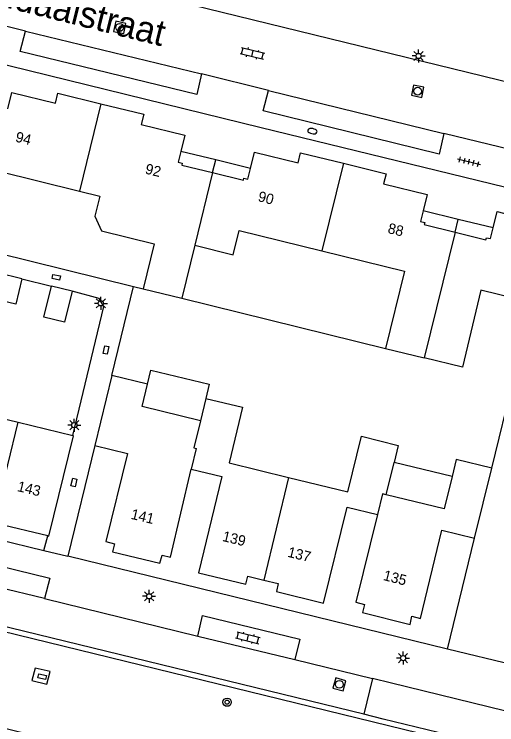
# Model space of a CAD drawing. Extents: x 125000 to 129004, y 397500 to 399008.
# Drawn here: x 126346.7 to 126393.1, y 398600 to 398668.3 of the extents above; entities that cross this region are included whole.
import ezdxf

# ---------------------------------------------------------------- set-up
doc = ezdxf.new("R2010")
doc.units = 0
for name, color, linetype in [('gg-afsc-erfafscheiding', 7, 'Continuous'), ('gg-afsc-hekwerk', 7, 'Continuous'), ('gg-afsc-muur', 7, 'Continuous'), ('gg-anno-huisnummerreeks BGT', 7, 'Continuous'), ('gg-anno-openbare ruimte label', 7, 'Continuous'), ('gg-bbg-bijgebouw', 7, 'Continuous'), ('gg-bbg-gedigitaliseerde bebouwing', 7, 'Continuous'), ('gg-bbg-hoofdgebouw', 7, 'Continuous'), ('gg-bbg-luifel en loopbrug', 7, 'Continuous'), ('gg-bbg-tussenscheiding', 7, 'Continuous'), ('gg-knt-verharding', 7, 'Continuous'), ('gg-knt-verharding nz', 7, 'Continuous'), ('gt-grn-weggrens', 7, 'Continuous'), ('gt-symb-boom', 7, 'Continuous'), ('gt-symb-brandkraan', 7, 'Continuous'), ('gt-symb-klinker verharding', 7, 'Continuous'), ('gt-symb-kolk center center', 7, 'Continuous'), ('gt-symb-lichtmast', 7, 'Continuous'), ('gt-symb-rioolschacht', 7, 'Continuous'), ('gt-symb-tegel verharding', 7, 'Continuous')]:
    doc.layers.add(name, color=color, linetype=linetype)

# ---------------------------------------------------------------- blocks, each defined once
blk = doc.blocks.new('gt0-RS')
at = {"layer": 'gt-symb-rioolschacht'}
blk.add_lwpolyline([(-0.5, -0.5), (0.5, -0.5), (0.5, 0.5), (-0.5, 0.5)], close=True, dxfattribs=at)
blk.add_circle((0, 0), 0.375, dxfattribs=at)
blk = doc.blocks.new('gt0-KL1')
at = {"layer": 'gt-symb-klinker verharding'}
for p, q in [((-1.15, 0.3), (1.15, 0.3)), ((-1, -0.3), (-1, 0.3)), ((-0.5, 0.3), (-0.5, 0.45)), ((0, -0.3), (0, 0.3)), ((0.5, 0.3), (0.5, 0.45)), ((1, -0.3), (1, 0.3)), ((-1.15, -0.3), (1.15, -0.3)), ((-0.5, -0.45), (-0.5, -0.3)), ((0.5, -0.45), (0.5, -0.3))]:
    blk.add_line(p, q, dxfattribs=at)
blk = doc.blocks.new('gt0-LMAST')
at = {"layer": 'gt-symb-lichtmast'}
for p, q in [((-0.182, 0.173), (-0.447, 0.438)), ((-0.005, 0.246), (-0.005, 0.621)), ((0.172, 0.173), (0.437, 0.438)), ((-0.255, -0.004), (-0.63, -0.004)), ((-0.182, -0.181), (-0.447, -0.446)), ((-0.005, -0.254), (-0.005, -0.629)), ((0.437, -0.446), (0.172, -0.181)), ((0.245, -0.004), (0.62, -0.004))]:
    blk.add_line(p, q, dxfattribs=at)
blk.add_circle((-0.005, -0.004), 0.25, dxfattribs=at)
blk = doc.blocks.new('gt0-BR')
at = {"layer": 'gt-symb-brandkraan'}
for centre, radius, start, end in [((-0.244, 0), 0.206, 107.56694, 252.43307), ((0.599, -2.664), 3, 106.89205, 107.56694), ((0, -0.691), 0.938, 73.10799, 106.89205), ((-0.599, -2.664), 3, 72.43309, 73.10799), ((0.244, 0), 0.206, 287.56695, 72.43309), ((0.599, 2.664), 3, 252.43307, 253.10797), ((0, 0.691), 0.938, 253.10797, 286.89206), ((-0.599, 2.664), 3, 286.89206, 287.56695)]:
    blk.add_arc(centre, radius, start, end, dxfattribs=at)
blk = doc.blocks.new('gt0-TEG1')
at = {"layer": 'gt-symb-tegel verharding'}
for p, q in [((-1.125, 0), (1.125, 0)), ((-0.9, -0.25), (-0.9, 0.25)), ((-0.45, -0.25), (-0.45, 0.25)), ((0, -0.25), (0, 0.25)), ((0.45, -0.25), (0.45, 0.25)), ((0.9, -0.25), (0.9, 0.25))]:
    blk.add_line(p, q, dxfattribs=at)
blk = doc.blocks.new('gt0-KOLKCC')
at = {"layer": 'gt-symb-kolk center center'}
blk.add_lwpolyline([(-0.375, 0.2), (0.375, 0.2), (0.375, -0.2), (-0.375, -0.2)], close=True, dxfattribs=at)
blk = doc.blocks.new('gt0-BOOM')
at = {"layer": 'gt-symb-boom'}
for radius in [0.4, 0.2]:
    blk.add_circle((0, 0), radius, dxfattribs=at)

msp = doc.modelspace()

# ---------------------------------------------------------------- linework, layer by layer
at = {"layer": 'gg-afsc-erfafscheiding'}
for p, q in [((126329.659, 398649.136), (126358.198, 398642.12)), ((126347.474, 398642.853), (126350.322, 398642.126)), ((126358.198, 398642.12), (126359.132, 398641.89)), ((126362.843, 398640.978), (126382.427, 398636.164))]:
    msp.add_line(p, q, dxfattribs=at)
at = {"layer": 'gg-afsc-hekwerk'}
msp.add_lwpolyline([(126352.367, 398627.785), (126355.364, 398640.183), (126354.91, 398640.94), (126352.302, 398641.651)], dxfattribs=at)
at = {"layer": 'gg-afsc-muur'}
msp.add_line((126356.117, 398633.543), (126358.198, 398642.12), dxfattribs=at)
msp.add_lwpolyline([(126392.667, 398624.659), (126394.743, 398633.172), (126398.49, 398632.245), (126400.229, 398639.654)], dxfattribs=at)
at = {"layer": 'gg-bbg-bijgebouw'}
for p, q in [((126347.474, 398642.853), (126344.904, 398643.478)), ((126352.302, 398641.651), (126350.322, 398642.126))]:
    msp.add_line(p, q, dxfattribs=at)
for points in [[(126347.474, 398642.853), (126346.877, 398640.395), (126344.307, 398641.02)], [(126352.302, 398641.651), (126351.576, 398638.691), (126349.595, 398639.177), (126350.322, 398642.126)]]:
    msp.add_lwpolyline(points, dxfattribs=at)
at = {"layer": 'gg-bbg-gedigitaliseerde bebouwing'}
for p, q in [((126345.045, 398653.233), (126353.009, 398651.272)), ((126353.009, 398651.272), (126354.951, 398650.794)), ((126360.199, 398646.216), (126359.132, 398641.89)), ((126364.1, 398646.075), (126362.843, 398640.978)), ((126359.132, 398641.89), (126362.843, 398640.978)), ((126359.03, 398630.577), (126359.552, 398632.717)), ((126365.151, 398631.352), (126364.629, 398629.212)), ((126364.629, 398629.212), (126359.03, 398630.577))]:
    msp.add_line(p, q, dxfattribs=at)
msp.add_lwpolyline([(126354.951, 398650.794), (126354.476, 398648.854), (126355.113, 398647.462), (126360.199, 398646.216)], dxfattribs=at)
at = {"layer": 'gg-bbg-hoofdgebouw'}
for p, q in [((126382.427, 398636.164), (126386.161, 398635.248)), ((126356.117, 398633.543), (126354.474, 398626.825)), ((126359.552, 398632.717), (126356.117, 398633.543)), ((126341.842, 398630.353), (126347.117, 398629.066)), ((126347.117, 398629.066), (126352.367, 398627.785)), ((126382.496, 398622.076), (126383.251, 398625.196)), ((126390.985, 398617.913), (126392.667, 398624.659)), ((126349.976, 398618.131), (126344.749, 398619.389))]:
    msp.add_line(p, q, dxfattribs=at)
for points in [[(126346.134, 398659.174), (126346.52, 398660.747), (126350.704, 398659.717), (126350.943, 398660.688), (126355.064, 398659.674)], [(126355.064, 398659.674), (126359.185, 398658.659), (126358.946, 398657.688), (126363.14, 398656.656), (126362.761, 398655.096)], [(126362.761, 398655.096), (126362.51, 398654.065), (126362.887, 398653.973), (126362.84, 398653.78), (126365.809, 398653.058)], [(126369.456, 398653.466), (126369.847, 398655.025), (126374.024, 398653.986), (126374.265, 398654.955), (126378.378, 398653.949)], [(126365.809, 398653.058), (126368.777, 398652.337), (126368.824, 398652.53), (126369.198, 398652.44), (126369.456, 398653.466)], [(126378.378, 398653.949), (126382.49, 398652.944), (126382.253, 398651.975), (126386.448, 398650.95), (126386.061, 398649.376)], [(126386.061, 398649.376), (126385.81, 398648.354), (126386.198, 398648.259), (126386.15, 398648.066), (126389.119, 398647.336)], [(126392.767, 398647.744), (126393.15, 398649.303), (126397.339, 398648.234), (126397.576, 398649.205), (126402.937, 398647.896), (126402.08, 398644.514), (126402.402, 398644.428), (126402.206, 398643.694), (126401.336, 398643.927), (126400.839, 398642.01)], [(126364.1, 398646.075), (126367.785, 398645.167), (126368.359, 398647.497), (126376.319, 398645.537)], [(126389.119, 398647.336), (126392.087, 398646.607), (126392.134, 398646.8), (126392.512, 398646.707), (126392.767, 398647.744)], [(126376.319, 398645.537), (126384.247, 398643.584), (126382.427, 398636.164)], [(126400.229, 398639.654), (126391.61, 398641.764), (126389.827, 398634.348), (126386.161, 398635.248)], [(126365.151, 398631.352), (126368.682, 398630.496), (126367.385, 398625.154), (126373.118, 398623.762)], [(126349.976, 398618.131), (126350.073, 398618.108), (126352.438, 398627.768), (126352.367, 398627.785)], [(126373.118, 398623.762), (126378.816, 398622.379), (126380.113, 398627.721), (126383.649, 398626.839), (126383.251, 398625.196)], [(126354.474, 398626.825), (126357.614, 398626.053), (126355.534, 398617.594), (126356.376, 398617.378), (126356.188, 398616.6), (126360.74, 398615.502), (126360.948, 398616.27), (126361.745, 398616.081), (126363.752, 398624.546)], [(126392.667, 398624.659), (126389.229, 398625.488), (126388.829, 398623.835)], [(126363.752, 398624.546), (126366.681, 398623.852), (126364.441, 398614.601), (126369.007, 398613.488), (126369.194, 398614.259), (126370.723, 398613.896)], [(126388.829, 398623.835), (126388.076, 398620.725), (126382.496, 398622.076)], [(126370.723, 398613.896), (126372.125, 398613.564), (126371.936, 398612.787), (126376.485, 398611.681), (126378.729, 398620.912), (126381.654, 398620.201)], [(126381.654, 398620.201), (126379.586, 398611.758), (126380.422, 398611.549), (126380.226, 398610.784), (126384.799, 398609.618), (126384.977, 398610.42), (126385.806, 398610.211), (126387.855, 398618.675), (126390.985, 398617.913)]]:
    msp.add_lwpolyline(points, dxfattribs=at)
at = {"layer": 'gg-bbg-luifel en loopbrug'}
for p, q in [((126366.107, 398654.282), (126362.761, 398655.096)), ((126365.809, 398653.058), (126366.107, 398654.282)), ((126369.456, 398653.466), (126366.107, 398654.282)), ((126389.417, 398648.56), (126386.061, 398649.376)), ((126389.119, 398647.336), (126389.417, 398648.56)), ((126392.767, 398647.744), (126389.417, 398648.56)), ((126388.829, 398623.835), (126383.251, 398625.196))]:
    msp.add_line(p, q, dxfattribs=at)
msp.add_lwpolyline([(126359.552, 398632.717), (126359.884, 398634.077), (126365.483, 398632.712), (126365.151, 398631.352)], dxfattribs=at)
at = {"layer": 'gg-bbg-tussenscheiding'}
for p, q in [((126355.064, 398659.674), (126353.009, 398651.272)), ((126378.378, 398653.949), (126376.319, 398645.537)), ((126365.809, 398653.058), (126364.1, 398646.075)), ((126389.119, 398647.336), (126386.161, 398635.248)), ((126344.749, 398619.389), (126347.117, 398629.066)), ((126373.118, 398623.762), (126370.723, 398613.896))]:
    msp.add_line(p, q, dxfattribs=at)
for points in [[(126364.629, 398629.212), (126363.99, 398626.589), (126364.236, 398626.529), (126363.752, 398624.546)], [(126382.496, 398622.076), (126382.131, 398622.165), (126381.654, 398620.201)]]:
    msp.add_lwpolyline(points, dxfattribs=at)
at = {"layer": 'gg-knt-verharding'}
for p, q in [((126404.05, 398659.327), (126267.231, 398692.82)), ((126347.83, 398666.647), (126341.393, 398668.237)), ((126371.195, 398660.94), (126364.746, 398662.547)), ((126394.504, 398655.235), (126388.047, 398656.822)), ((126281.081, 398633.48), (126349.59, 398616.724)), ((126354.474, 398626.825), (126351.88, 398616.184)), ((126380.349, 398600.989), (126279.553, 398625.612)), ((126349.59, 398616.724), (126349.976, 398618.131)), ((126388.39, 398607.26), (126390.985, 398617.913)), ((126388.39, 398607.26), (126351.88, 398616.184)), ((126349.653, 398612.11), (126364.385, 398608.508)), ((126405.897, 398603.002), (126388.39, 398607.26)), ((126373.699, 398606.256), (126381.166, 398604.433)), ((126381.166, 398604.433), (126380.349, 398600.989))]:
    msp.add_line(p, q, dxfattribs=at)
for points in [[(126401.744, 398649.736), (126370.487, 398657.358), (126323.892, 398668.809), (126286.162, 398678.033), (126285.184, 398678.288)], [(126364.746, 398662.547), (126364.288, 398660.55), (126347.321, 398664.706), (126347.83, 398666.647)], [(126388.047, 398656.822), (126387.585, 398654.844), (126370.67, 398658.991), (126371.195, 398660.94)], [(126251.111, 398622.776), (126385.016, 398590.066), (126389.442, 398592.774), (126389.826, 398594.31), (126387.158, 398598.804), (126253.25, 398631.546)], [(126291.279, 398628.476), (126350.149, 398614.074), (126349.653, 398612.11)], [(126364.385, 398608.508), (126364.85, 398610.495), (126374.178, 398608.204), (126373.699, 398606.256)], [(126349.878, 398603.895), (126350.201, 398605.091), (126348.756, 398605.433), (126348.433, 398604.238), (126349.878, 398603.895)], [(126409.82, 398597.415), (126408.002, 398597.874), (126383.022, 398603.965), (126381.166, 398604.433)], [(126377.976, 398591.273), (126385.099, 398589.531), (126389.878, 398592.454), (126390.361, 398594.388), (126387.48, 398599.24), (126382.194, 398600.521), (126380.349, 398600.989)]]:
    msp.add_lwpolyline(points, dxfattribs=at)
at = {"layer": 'gg-knt-verharding nz'}
for p, q in [((126347.83, 398666.647), (126364.746, 398662.547)), ((126371.195, 398660.94), (126388.047, 398656.822)), ((126349.653, 398612.11), (126290.853, 398626.513)), ((126364.385, 398608.508), (126373.699, 398606.256))]:
    msp.add_line(p, q, dxfattribs=at)
at = {"layer": 'gt-grn-weggrens'}
msp.add_line((126349.59, 398616.724), (126351.88, 398616.184), dxfattribs=at)

# ---------------------------------------------------------------- block references
at = {"layer": 'gt-symb-boom'}
msp.add_blockref('gt0-BOOM', (126367.205, 398602.154), dxfattribs=at)
at = {"layer": 'gt-symb-brandkraan', "rotation": 168.11724113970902}
msp.add_blockref('gt0-BR', (126375.401, 398657.044), dxfattribs=at)
at = {"layer": 'gt-symb-klinker verharding'}
for p, rotation in [((126369.644, 398664.517), -13.772145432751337), ((126369.199, 398608.341), -13.758515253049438)]:
    msp.add_blockref('gt0-KL1', p, dxfattribs=dict(at, rotation=rotation))
at = {"layer": 'gt-symb-kolk center center'}
for p, rotation in [((126350.776, 398642.999), 168.75747429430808), ((126355.554, 398636.002), -101.53462065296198), ((126352.472, 398623.275), 76.99249520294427), ((126349.416, 398604.61), -11.714525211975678)]:
    msp.add_blockref('gt0-KOLKCC', p, dxfattribs=dict(at, rotation=rotation))
at = {"layer": 'gt-symb-lichtmast'}
for p in [(126385.61, 398664.271), (126355.076, 398640.495), (126352.519, 398628.784), (126359.705, 398612.333), (126384.123, 398606.39)]:
    msp.add_blockref('gt0-LMAST', p, dxfattribs=at)
at = {"layer": 'gt-symb-rioolschacht'}
for p, rotation in [((126356.876, 398667.013), -12.118760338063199), ((126385.516, 398660.879), -11.242525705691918), ((126377.996, 398603.864), -15.425970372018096)]:
    msp.add_blockref('gt0-RS', p, dxfattribs=dict(at, rotation=rotation))
at = {"layer": 'gt-symb-tegel verharding', "rotation": -13.772145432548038}
msp.add_blockref('gt0-TEG1', (126390.459, 398654.104), dxfattribs=at)

# ---------------------------------------------------------------- texts
at = {"layer": 'gg-anno-huisnummerreeks BGT'}
for s, rotation, p in [('94', 346.2, (126346.786, 398656.046)), ('92', 346.2, (126359.26, 398652.975)), ('90', 346, (126370.105, 398650.324)), ('88', 346.3, (126382.579, 398647.262)), ('143', 346.5, (126346.964, 398622.455)), ('141', 346.5, (126357.888, 398619.789)), ('139', 346.3, (126366.679, 398617.658)), ('137', 346.4, (126372.954, 398616.14)), ('135', 345.7, (126382.147, 398613.906))]:
    msp.add_text(s, height=1, rotation=rotation, dxfattribs=at).set_placement(p)
at = {"layer": 'gg-anno-openbare ruimte label'}
msp.add_text('Voerendaalstraat', height=2.5, rotation=346, dxfattribs=at).set_placement((126336.192, 398671.351))

doc.saveas('drawing.dxf')
